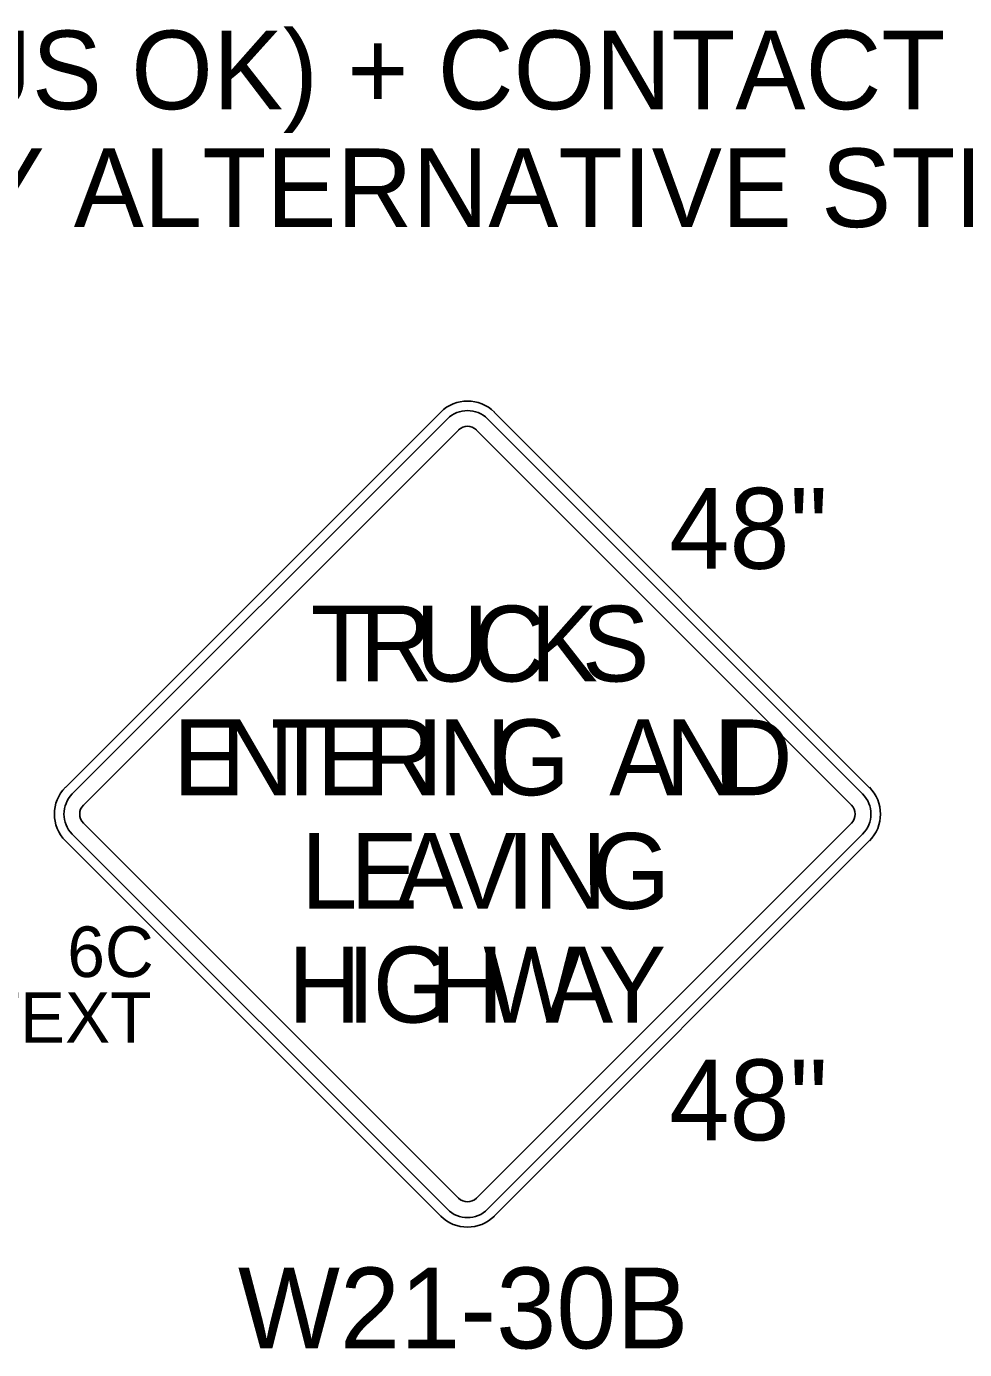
# Model space of a CAD drawing. Extents: x 99999 to 100116, y 99995 to 100013.
# Drawn here: x 100033.098 to 100033.934, y 100001.176 to 100002.354 of the extents above; entities that cross this region are included whole.
import ezdxf

# ---------------------------------------------------------------- set-up
doc = ezdxf.new("R2010")
doc.units = 0
doc.layers.add('SH_GI_GeneralNotesBodyText', color=7, linetype='Continuous')
doc.layers.add('TR_SN_ConstructionSigns', color=7, linetype='Continuous')

msp = doc.modelspace()

# ---------------------------------------------------------------- linework, layer by layer
at = {"layer": 'TR_SN_ConstructionSigns'}
for p, q in [((100033.4669, 100002.0107), (100033.1328, 100001.6766)), ((100033.8487, 100001.6766), (100033.5146, 100002.0107)), ((100033.4729, 100002.0048), (100033.1387, 100001.6707)), ((100033.1487, 100001.6607), (100033.4828, 100001.9948)), ((100033.4987, 100001.9948), (100033.8328, 100001.6607)), ((100033.8428, 100001.6707), (100033.5087, 100002.0048)), ((100033.4828, 100001.3107), (100033.1487, 100001.6448)), ((100033.8328, 100001.6448), (100033.4987, 100001.3107)), ((100033.1328, 100001.6289), (100033.4669, 100001.2948)), ((100033.1387, 100001.6349), (100033.4729, 100001.3008)), ((100033.5087, 100001.3008), (100033.8428, 100001.6349)), ((100033.5146, 100001.2948), (100033.8487, 100001.6289))]:
    msp.add_line(p, q, dxfattribs=at)
for centre, radius, start, end in [((100033.4908, 100001.9869), 0.0338, 45, 135), ((100033.4908, 100001.9869), 0.0253, 45, 135), ((100033.4908, 100001.9869), 0.0113, 45, 135), ((100033.1566, 100001.6528), 0.0338, 135, 225), ((100033.8249, 100001.6528), 0.0338, 315, 45), ((100033.1566, 100001.6528), 0.0253, 135, 225), ((100033.8249, 100001.6528), 0.0253, 315, 45), ((100033.1566, 100001.6528), 0.0113, 135, 225), ((100033.8249, 100001.6528), 0.0113, 315, 45), ((100033.4908, 100001.3187), 0.0113, 225, 315), ((100033.4908, 100001.3187), 0.0253, 225, 315), ((100033.4908, 100001.3187), 0.0338, 225, 315)]:
    msp.add_arc(centre, radius, start, end, dxfattribs=at)

# ---------------------------------------------------------------- texts
at = {"layer": 'SH_GI_GeneralNotesBodyText'}
for s, p in [('(WORK TRUCK, VAN, OR BUS OK) + CONTACT INFORMATION OR PHONE BOX.', (100031.839, 100002.2806)), ('(C) ENGINEER TO ACCEPT ANY ALTERNATIVE STRATEGIES.', (100031.689, 100002.1756))]:
    msp.add_text(s, height=0.07, rotation=360, dxfattribs=at).set_placement(p)
at = {"layer": 'TR_SN_ConstructionSigns'}
for s, p in [('48"', (100033.6706, 100001.8713)), ('48"', (100033.6706, 100001.3622)), ('W21-30B', (100033.2863, 100001.1769))]:
    msp.add_text(s, height=0.072, rotation=360, dxfattribs=at).set_placement(p)
for s, height, p in [('T', 0.0675, (100033.351, 100001.7709)), ('R', 0.0675, (100033.3949, 100001.7709)), ('U', 0.0675, (100033.4442, 100001.7709)), ('C', 0.0675, (100033.4955, 100001.7709)), ('K', 0.0675, (100033.5468, 100001.7709)), ('S', 0.0675, (100033.5927, 100001.7709)), ('E', 0.0675, (100033.2286, 100001.6696)), ('N', 0.0675, (100033.271, 100001.6696)), ('T', 0.0675, (100033.3154, 100001.6696)), ('E', 0.0675, (100033.3565, 100001.6696)), ('R', 0.0675, (100033.3989, 100001.6696)), ('I', 0.0675, (100033.4448, 100001.6696)), ('N', 0.0675, (100033.4646, 100001.6696)), ('G', 0.0675, (100033.5118, 100001.6696)), ('A', 0.0675, (100033.6171, 100001.6696)), ('N', 0.0675, (100033.667, 100001.6696)), ('D', 0.0675, (100033.7152, 100001.6696)), ('L', 0.0675, (100033.3426, 100001.5684)), ('E', 0.0675, (100033.3865, 100001.5684)), ('A', 0.0675, (100033.427, 100001.5684)), ('V', 0.0675, (100033.4742, 100001.5684)), ('I', 0.0675, (100033.5255, 100001.5684)), ('N', 0.0675, (100033.5498, 100001.5684)), ('G', 0.0675, (100033.6011, 100001.5684)), ('6C', 0.045, (100033.1343, 100001.5077)), ('H', 0.0675, (100033.3308, 100001.4671)), ('I', 0.0675, (100033.3834, 100001.4671)), ('G', 0.0675, (100033.4064, 100001.4671)), ('H', 0.0675, (100033.4577, 100001.4671)), ('W', 0.0675, (100033.5049, 100001.4671)), ('A', 0.0675, (100033.5603, 100001.4671)), ('Y', 0.0675, (100033.6075, 100001.4671)), ('TEXT', 0.045, (100033.0554, 100001.4491))]:
    msp.add_text(s, height=height, dxfattribs=at).set_placement(p)

doc.saveas('drawing.dxf')
